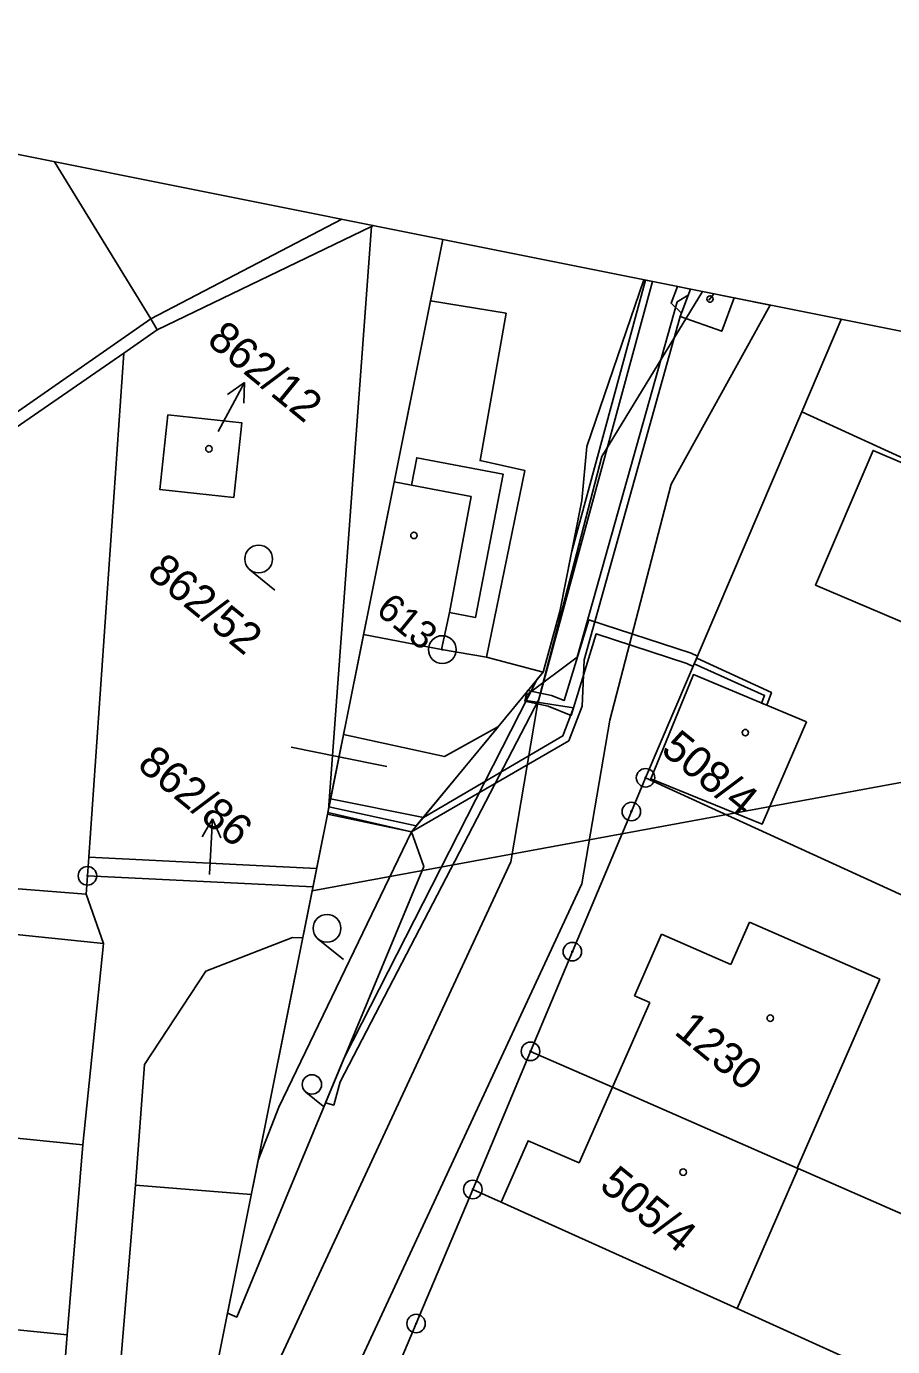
# Model space of a CAD drawing. Extents: x -548552 to -543113, y -1131925 to -1123599.
# Drawn here: x -547984.1 to -547937.2, y -1130029.4 to -1129958.1 of the extents above; entities that cross this region are included whole.
import ezdxf

# ---------------------------------------------------------------- set-up
doc = ezdxf.new("R2010")
doc.units = 0
for name, color, linetype in [('Hranice parcel', 7, 'Continuous'), ('Parcelní čísla', 7, 'Continuous'), ('Pop  PČ popisy', 7, 'Continuous'), ('Profile', 7, 'Continuous'), ('SVAHY', 7, 'Continuous'), ('Vnitřní kresba', 7, 'Continuous'), ('Věcná břemena k části', 7, 'Continuous'), ('Značky bodu BP', 7, 'Continuous'), ('Značky budov', 7, 'Continuous'), ('Značky kultur', 7, 'Continuous')]:
    doc.layers.add(name, color=color, linetype=linetype)

msp = doc.modelspace()

# ---------------------------------------------------------------- linework, layer by layer
at = {"layer": 'Hranice parcel'}
for p, q in [((-547982.562, -1129965.371), (-547977.361, -1129973.877)), ((-547965.418, -1129968.876), (-547977.01, -1129974.46)), ((-547967.76, -1130000.415), (-547965.418, -1129968.876)), ((-547977.01, -1129974.46), (-547978.822, -1129975.718)), ((-547977.361, -1129973.877), (-547977.01, -1129974.46)), ((-547940.026, -1129973.897), (-547942.159, -1129978.894)), ((-547978.822, -1129975.718), (-547992.872, -1129985.413)), ((-547978.822, -1129975.718), (-547980.714, -1130002.978)), ((-547942.159, -1129978.894), (-547950.607, -1129998.685)), ((-547959.212, -1129992.165), (-547956.138, -1129992.967)), ((-547956.138, -1129992.967), (-547963.266, -1130001.606)), ((-547950.607, -1129998.685), (-547923.429, -1130011.112)), ((-547963.266, -1130001.606), (-547967.809, -1130000.661)), ((-547980.789, -1130003.988), (-547980.714, -1130002.978)), ((-547980.714, -1130002.978), (-547968.397, -1130003.593)), ((-547998.811, -1130003.533), (-547980.865, -1130004.984)), ((-547980.789, -1130003.988), (-547980.865, -1130004.984)), ((-547968.594, -1130004.575), (-547980.789, -1130003.988)), ((-547980.865, -1130004.984), (-547979.918, -1130007.638)), ((-547979.918, -1130007.638), (-547998.921, -1130005.727)), ((-547979.918, -1130007.638), (-547981.036, -1130018.542)), ((-547959.947, -1130020.948), (-547956.829, -1130013.479)), ((-547981.036, -1130018.542), (-548020.177, -1130014.594)), ((-547981.036, -1130018.542), (-547981.878, -1130028.806)), ((-547942.357, -1130019.813), (-547945.656, -1130027.392)), ((-547979.441, -1130035.552), (-547978.191, -1130020.718)), ((-547971.929, -1130021.216), (-547978.191, -1130020.718)), ((-547887.202, -1130053.755), (-547945.656, -1130027.392)), ((-547981.878, -1130028.806), (-547982.716, -1130038.907))]:
    msp.add_line(p, q, dxfattribs=at)
for points in [[(-547965.316, -1129968.827), (-547965.418, -1129968.876)], [(-547956.138, -1129992.967), (-547955.236, -1129989.69), (-547954.051, -1129983.691), (-547953.787, -1129980.771), (-547950.696, -1129971.758)], [(-547945.823, -1129972.735), (-547946.484, -1129974.545), (-547948.727, -1129973.736), (-547948.18, -1129972.262)], [(-547959.212, -1129992.165), (-547957.138, -1129982.066), (-547959.552, -1129981.53), (-547958.148, -1129973.568), (-547962.244, -1129972.899)], [(-547976.44, -1129979.065), (-547976.882, -1129983.09), (-547972.864, -1129983.525), (-547972.43, -1129979.494), (-547976.44, -1129979.065)], [(-547942.159, -1129978.894), (-547928.917, -1129984.947), (-547928.16, -1129985.951)], [(-547919.53, -1129997.302), (-547925.837, -1130001.528), (-547932.38, -1129992.096), (-547931.821, -1129990.824), (-547933.513, -1129990.051), (-547934.079, -1129991.396), (-547941.408, -1129988.263), (-547938.299, -1129980.98), (-547931, -1129984.101), (-547931.217, -1129984.621), (-547928.16, -1129985.951)], [(-547965.86, -1129990.935), (-547961.644, -1129991.745), (-547959.212, -1129992.165)], [(-547941.911, -1129995.657), (-547944.309, -1130001.197), (-547950.325, -1129998.734), (-547948.021, -1129993.104), (-547941.911, -1129995.657)], [(-547956.829, -1130013.479), (-547954.565, -1130008.088), (-547951.373, -1130000.512), (-547950.607, -1129998.685)], [(-547973.216, -1130027.637), (-547972.712, -1130027.846), (-547970.072, -1130021.471), (-547962.605, -1130003.486), (-547963.266, -1130001.606)], [(-547971.559, -1130019.371), (-547970.439, -1130016.49), (-547963.266, -1130001.606)], [(-547978.191, -1130020.718), (-547977.699, -1130014.192), (-547974.384, -1130009.141), (-547969.701, -1130007.319), (-547969.15, -1130007.349)], [(-547956.829, -1130013.479), (-547952.387, -1130015.421), (-547942.402, -1130019.789), (-547942.357, -1130019.813)], [(-547942.357, -1130019.813), (-547929.672, -1130025.362), (-547925.095, -1130027.375)], [(-547959.947, -1130020.948), (-547963.016, -1130028.199), (-547965.396, -1130033.844)], [(-547945.656, -1130027.392), (-547958.419, -1130021.638), (-547959.947, -1130020.948)], [(-547981.878, -1130028.806), (-548019.313, -1130025.075), (-548019.815, -1130025.026)]]:
    msp.add_lwpolyline(points, dxfattribs=at)
at = {"layer": 'Pop  PČ popisy'}
for p, q in [((-547947.181, -1129972.867), (-547947.025, -1129972.66)), ((-547947.025, -1129972.66), (-547946.919, -1129972.515)), ((-547973.711, -1129979.959), (-547972.295, -1129977.313)), ((-547972.295, -1129977.313), (-547973.209, -1129977.96)), ((-547972.295, -1129977.313), (-547972.326, -1129978.433)), ((-547974.022, -1130000.9), (-547974.577, -1130001.873)), ((-547974.188, -1130003.897), (-547974.022, -1130000.9)), ((-547974.022, -1130000.9), (-547973.577, -1130001.928)), ((-547974.192, -1130003.919), (-547974.188, -1130003.897))]:
    msp.add_line(p, q, dxfattribs=at)
at = {"layer": 'Profile'}
for p, q in [((-548019.049, -1129958.057), (-547961.578, -1129969.577)), ((-547961.578, -1129969.577), (-547980.408, -1130063.514)), ((-547967.187, -1129997.556), (-547969.776, -1129997.037)), ((-547964.598, -1129998.075), (-547967.187, -1129997.556)), ((-547968.64, -1130004.808), (-548003.516, -1130178.797))]:
    msp.add_line(p, q, dxfattribs=at)
at = {"layer": 'SVAHY'}
for p, q in [((-547961.578, -1129969.577), (-547968.64, -1130004.808)), ((-547961.578, -1129969.577), (-547873.446, -1129987.243)), ((-547968.64, -1130004.808), (-547873.446, -1129987.243))]:
    msp.add_line(p, q, dxfattribs=at)
at = {"layer": 'Vnitřní kresba'}
for p, q in [((-547967.033, -1129968.483), (-547977.361, -1129973.877)), ((-547977.361, -1129973.877), (-547993.189, -1129984.884)), ((-547964.207, -1129982.688), (-547963.269, -1129982.862)), ((-547963.269, -1129982.862), (-547960.036, -1129983.471)), ((-547961.201, -1129989.745), (-547960.036, -1129983.471)), ((-547961.644, -1129991.745), (-547961.201, -1129989.745)), ((-547945.986, -1130008.782), (-547944.983, -1130006.491)), ((-547944.983, -1130006.491), (-547937.93, -1130009.58)), ((-547951.208, -1130010.474), (-547949.743, -1130007.14)), ((-547949.743, -1130007.14), (-547945.986, -1130008.782)), ((-547937.93, -1130009.58), (-547942.402, -1130019.789)), ((-547952.387, -1130015.421), (-547950.382, -1130010.838)), ((-547950.382, -1130010.838), (-547951.208, -1130010.474))]:
    msp.add_line(p, q, dxfattribs=at)
for points in [[(-547961.201, -1129989.745), (-547959.795, -1129990.014), (-547958.303, -1129982.277), (-547962.979, -1129981.383), (-547963.269, -1129982.862)], [(-547958.419, -1130021.638), (-547956.961, -1130018.312), (-547954.202, -1130019.501), (-547952.387, -1130015.421)]]:
    msp.add_lwpolyline(points, dxfattribs=at)
at = {"layer": 'Věcná břemena k části'}
for p, q in [((-547950.225, -1129971.852), (-547950.616, -1129971.774)), ((-547950.225, -1129971.852), (-547950.616, -1129971.774)), ((-547948.181, -1129972.262), (-547948.885, -1129972.121)), ((-547948.181, -1129972.262), (-547948.885, -1129972.121)), ((-547943.87, -1129973.126), (-547947.53, -1129972.393)), ((-547966.943, -1129996.339), (-547967.728, -1130000.257)), ((-547967.643, -1129999.831), (-547967.789, -1130000.562))]:
    msp.add_line(p, q, dxfattribs=at)
for points in [[(-547950.616, -1129971.774), (-547954.608, -1129986.513), (-547955.236, -1129989.69), (-547956.138, -1129992.967), (-547956.46, -1129993.362), (-547966.901, -1130013.826), (-547967.91, -1130016.267), (-547967.464, -1130016.385), (-547967.13, -1130015.136), (-547956.384, -1129994.456), (-547950.225, -1129971.852)], [(-547950.616, -1129971.774), (-547954.608, -1129986.513), (-547955.236, -1129989.69), (-547956.138, -1129992.967), (-547956.46, -1129993.362), (-547966.901, -1130013.826), (-547967.91, -1130016.267), (-547967.464, -1130016.385), (-547967.13, -1130015.136), (-547956.384, -1129994.456), (-547950.225, -1129971.852)], [(-547948.885, -1129972.121), (-547949.227, -1129973.02), (-547948.666, -1129973.566), (-547948.181, -1129972.262)], [(-547948.885, -1129972.121), (-547949.227, -1129973.02), (-547948.666, -1129973.566), (-547948.181, -1129972.262)], [(-547947.53, -1129972.393), (-547952.964, -1129981.312), (-547956.449, -1129994.725), (-547957.891, -1130003.224), (-547971.125, -1130031.693), (-547972.502, -1130033.035), (-547973.557, -1130035.296), (-547973.252, -1130037.376), (-547976.859, -1130045.812)], [(-547967.789, -1130000.562), (-547963.266, -1130001.606), (-547954.756, -1129996.685), (-547954.038, -1129994.806), (-547953.93, -1129992.315), (-547948.727, -1129973.736), (-547948.303, -1129972.598), (-547948.9, -1129972.951), (-547954.301, -1129992.168), (-547957.028, -1129994.202), (-547957.068, -1129994.504), (-547954.511, -1129994.911), (-547955.082, -1129996.42), (-547962.621, -1130000.829), (-547967.643, -1129999.831)], [(-547980.699, -1130064.965), (-547969.118, -1130037.906), (-547969.43, -1130035.898), (-547967.8, -1130034.04), (-547954.044, -1130004.424), (-547952.539, -1129995.563), (-547949.229, -1129982.807), (-547943.87, -1129973.126)], [(-547967.728, -1130000.257), (-547963.007, -1130001.288), (-547958.566, -1129995.916), (-547961.472, -1129997.534), (-547966.943, -1129996.339)]]:
    msp.add_lwpolyline(points, dxfattribs=at)
for points in [[(-547954.633, -1129995.315), (-547953.285, -1129990.905), (-547948.366, -1129992.514), (-547948.037, -1129992.665), (-547947.974, -1129992.523), (-547947.841, -1129992.219), (-547947.803, -1129992.108), (-547948.139, -1129991.95), (-547953.675, -1129990.149), (-547955.013, -1129994.515), (-547955.695, -1129994.243), (-547956.967, -1129993.968), (-547957.024, -1129994.038), (-547957.128, -1129994.546), (-547955.878, -1129994.816)], [(-547947.841, -1129992.219), (-547947.974, -1129992.523), (-547944.173, -1129994.239), (-547944.338, -1129994.647), (-547944.056, -1129994.76), (-547943.799, -1129994.08)]]:
    msp.add_lwpolyline(points, close=True, dxfattribs=at)
at = {"layer": 'Značky bodu BP'}
for centre, radius in [((-547961.6, -1129991.754), 0.75), ((-547961.6, -1129991.754), 0.03), ((-547950.607, -1129998.685), 0.5), ((-547950.607, -1129998.685), 0.0303), ((-547951.373, -1130000.512), 0.5), ((-547951.373, -1130000.512), 0.0303), ((-547980.788, -1130003.988), 0.5), ((-547980.788, -1130003.988), 0.0303), ((-547954.565, -1130008.088), 0.5), ((-547954.565, -1130008.088), 0.0303), ((-547956.829, -1130013.479), 0.5), ((-547956.829, -1130013.479), 0.0303), ((-547959.947, -1130020.948), 0.5), ((-547959.947, -1130020.948), 0.0303), ((-547963.016, -1130028.199), 0.5), ((-547963.016, -1130028.199), 0.0303)]:
    msp.add_circle(centre, radius, dxfattribs=at)
at = {"layer": 'Značky budov'}
for centre in [(-547947.121, -1129972.799), (-547974.217, -1129980.9), (-547963.13, -1129985.579), (-547945.21, -1129996.245), (-547943.86, -1130011.687), (-547948.575, -1130020.009)]:
    msp.add_circle(centre, 0.175, dxfattribs=at)
at = {"layer": 'Značky kultur'}
for p, q in [((-547972.004, -1129987.437), (-547970.648, -1129988.543)), ((-547968.305, -1130007.407), (-547966.948, -1130008.512)), ((-547968.983, -1130015.677), (-547968.033, -1130016.45))]:
    msp.add_line(p, q, dxfattribs=at)
for centre, radius in [((-547971.53, -1129986.856), 0.75), ((-547967.831, -1130006.825), 0.75), ((-547968.651, -1130015.27), 0.525)]:
    msp.add_circle(centre, radius, dxfattribs=at)

# ---------------------------------------------------------------- texts
at = {"layer": 'Parcelní čísla'}
for s, p in [('862/12', (-547974.394, -1129975.164)), ('862/52', (-547977.642, -1129987.733)), ('508/4', (-547949.846, -1129997.292)), ('862/86', (-547978.167, -1129998.114)), ('1230', (-547949.121, -1130012.497)), ('505/4', (-547953.174, -1130020.855))]:
    msp.add_text(s, height=1.7, rotation=320.83233, dxfattribs=at).set_placement(p)
at = {"layer": 'Značky bodu BP'}
msp.add_text('613', height=1.5, rotation=320.83233, dxfattribs=at).set_placement((-547965.255, -1129989.745))

doc.saveas('drawing.dxf')
